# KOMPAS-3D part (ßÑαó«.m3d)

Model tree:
1. Эскиз:1
2. Операция выдавливания:1
     Расстояние 1 = 22.4; Расстояние 2 = 7.2
3. Эскиз:2
4. Операция выдавливания:2
     Расстояние 1 = 1; Расстояние 2 = 7.2
5. Эскиз:7
6. Вырезать элемент выдавливания:3
     Расстояние 1 = 3
7. Скругление:1
     Радиус = 1

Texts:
  stalker61
  Полипропилен  ГОСТ 26996-86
